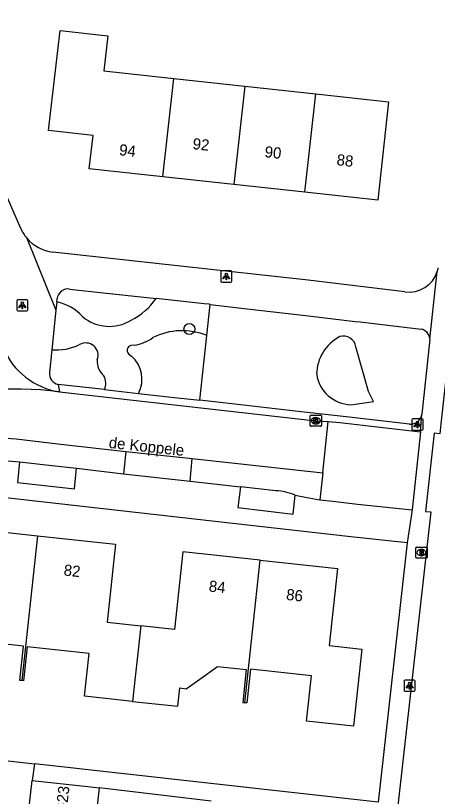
# Model space of a CAD drawing. Extents: x 162026 to 163499, y 387297 to 388169.
# Drawn here: x 162240.9 to 162278.6, y 387793.2 to 387863.1 of the extents above; entities that cross this region are included whole.
import ezdxf

# ---------------------------------------------------------------- set-up
doc = ezdxf.new("R2010")
doc.units = 0
for name, color, linetype in [('IMGEO_Boom', 7, 'Continuous'), ('IMGEO_Brandkraan', 7, 'Continuous'), ('IMGEO_Fietspad_gesloten', 7, 'Continuous'), ('IMGEO_Groenvoorziening', 7, 'Continuous'), ('IMGEO_Kolk', 7, 'Continuous'), ('IMGEO_Lichtpunt', 7, 'Continuous'), ('IMGEO_Openbare_ruimte_label', 7, 'Continuous'), ('IMGEO_Pand', 7, 'Continuous'), ('IMGEO_Pand_nummerreeks', 7, 'Continuous'), ('IMGEO_Parkeervlak_open', 7, 'Continuous'), ('IMGEO_Rijbaan_lokaal_open', 7, 'Continuous'), ('IMGEO_Voetpad_open', 7, 'Continuous')]:
    doc.layers.add(name, color=color, linetype=linetype)

msp = doc.modelspace()

# ---------------------------------------------------------------- linework, layer by layer
at = {"layer": 'IMGEO_Boom'}
msp.add_circle((162256.452, 387835.043), 0.489, dxfattribs=at)
at = {"layer": 'IMGEO_Brandkraan'}
for p, q in [((162276.715, 387814.598), (162276.715, 387815.45)), ((162276.79, 387815.524), (162277.642, 387815.524)), ((162277.203, 387815.304), (162277.228, 387815.304)), ((162277.716, 387815.45), (162277.716, 387814.598)), ((162277.642, 387814.524), (162276.79, 387814.524)), ((162277.226, 387814.744), (162277.201, 387814.744))]:
    msp.add_line(p, q, dxfattribs=at)
for points in [[(162276.715, 387814.598), (162276.715, 387815.45)], [(162276.79, 387815.524), (162277.642, 387815.524)], [(162277.063, 387815.224), (162277.063, 387814.824), (162277.276, 387814.824)], [(162277.294, 387815.224), (162277.063, 387815.224)], [(162277.242, 387815.143), (162277.188, 387815.143), (162277.188, 387815.067)], [(162277.188, 387815.067), (162277.241, 387815.067)], [(162277.25, 387814.991), (162277.188, 387814.991), (162277.188, 387814.91)], [(162277.188, 387814.91), (162277.25, 387814.91)], [(162277.716, 387815.45), (162277.716, 387814.598)], [(162277.642, 387814.524), (162276.79, 387814.524)]]:
    msp.add_lwpolyline(points, dxfattribs=at)
for centre, radius, start, end in [((162276.792, 387815.448), 0.0765, 91.55205, 178.44795), ((162276.792, 387815.448), 0.0765, 91.55205, 178.44795), ((162277.243, 387815.105), 0.0379, 267.82845, 90.93552), ((162277.251, 387814.95), 0.0404, 269.87594, 90.50774), ((162277.298, 387815.079), 0.145, 59.4692, 91.53667), ((162277.323, 387815.126), 0.0922, 285.51372, 58.15012), ((162277.328, 387814.934), 0.105, 301.31148, 78.98903), ((162277.64, 387815.448), 0.0765, 1.55205, 88.44795), ((162277.64, 387815.448), 0.0765, 1.55205, 88.44795), ((162276.792, 387814.6), 0.0765, 181.55205, 268.44795), ((162276.792, 387814.6), 0.0765, 181.55205, 268.44795), ((162277.282, 387815.075), 0.251, 268.66757, 293.53466), ((162277.64, 387814.6), 0.0765, 271.55205, 358.44795), ((162277.64, 387814.6), 0.0765, 271.55205, 358.44795)]:
    msp.add_arc(centre, radius, start, end, dxfattribs=at)
for centre, major_axis, ratio, start_param, end_param in [((162277.202, 387815.024), (-0.387, 0.002), 0.722429, 4.712389, 7.853982), ((162277.227, 387815.024), (-0.39, 0.002), 0.717154, 1.570796, 4.712389)]:
    msp.add_ellipse(centre, major_axis=major_axis, ratio=ratio, start_param=start_param, end_param=end_param, dxfattribs=at)
at = {"layer": 'IMGEO_Fietspad_gesloten'}
msp.add_lwpolyline([(162296.034, 387979.848), (162290.464, 387929.711), (162288.097, 387908.488), (162278.956, 387826.545), (162278.87, 387825.665), (162278.372, 387825.72), (162277.589, 387818.699), (162278.067, 387818.669), (162270.183, 387748.502), (162261.381, 387669.505), (162260.87, 387664.615)], dxfattribs=at)
at = {"layer": 'IMGEO_Groenvoorziening'}
for points in [[(162257.994, 387834.455), (162258.294, 387837.248)], [(162257.372, 387828.658), (162257.994, 387834.455)], [(162251.508, 387833.59), (162251.198, 387833.553)], [(162270.892, 387828.269), (162272.94, 387828.554), (162272.489, 387829.458), (162271.358, 387833.459)], [(162250.993, 387832.822), (162251.269, 387832.606)]]:
    msp.add_lwpolyline(points, dxfattribs=at)
for centre, radius, start, end in [((162243.587, 387833.056), 4.527, 43.12046, 77.31501), ((162248.633, 387841.065), 5.841, 296.30783, 325.7774), ((162249.278, 387838.98), 3.702, 229.84877, 301.67357), ((162255.79, 387829.102), 5.789, 67.62357, 116.82366), ((162247.173, 387832.697), 1.098, 338.10227, 120.25238), ((162250.942, 387837.38), 3.832, 278.49298, 305.70015), ((162271.67, 387830.955), 3.831, 117.34239, 179.37605), ((162270.237, 387833.268), 1.138, 9.66245, 106.63339), ((162244.497, 387838.155), 4.985, 265.75481, 295.20673), ((162251.303, 387833.129), 0.437, 103.96615, 224.70284), ((162249.478, 387830.551), 2.726, 332.17177, 48.93446), ((162249.938, 387832.173), 1.75, 176.27334, 229.34419), ((162270.985, 387831.444), 3.177, 188.09455, 268.32221), ((162247.631, 387830.2), 1.334, 334.40012, 28.972)]:
    msp.add_arc(centre, radius, start, end, dxfattribs=at)
at = {"layer": 'IMGEO_Kolk'}
for p, q in [((162267.268, 387826.407), (162267.268, 387827.259)), ((162267.343, 387827.333), (162268.195, 387827.333)), ((162267.756, 387827.113), (162267.781, 387827.113)), ((162268.269, 387827.259), (162268.269, 387826.407)), ((162268.195, 387826.333), (162267.343, 387826.333)), ((162267.779, 387826.553), (162267.754, 387826.553))]:
    msp.add_line(p, q, dxfattribs=at)
for points in [[(162267.268, 387826.407), (162267.268, 387827.259)], [(162267.343, 387827.333), (162268.195, 387827.333)], [(162267.589, 387827.033), (162267.712, 387827.033), (162267.712, 387826.882), (162267.842, 387827.033), (162268.006, 387827.033), (162267.86, 387826.882), (162268.013, 387826.633), (162267.861, 387826.633), (162267.776, 387826.797), (162267.712, 387826.73), (162267.712, 387826.633), (162267.589, 387826.633), (162267.589, 387827.033)], [(162268.269, 387827.259), (162268.269, 387826.407)], [(162268.195, 387826.333), (162267.343, 387826.333)]]:
    msp.add_lwpolyline(points, dxfattribs=at)
for centre, start, end in [((162267.345, 387827.257), 91.55205, 178.44795), ((162267.345, 387827.257), 91.55205, 178.44795), ((162268.193, 387827.257), 1.55205, 88.44795), ((162268.193, 387827.257), 1.55205, 88.44795), ((162267.345, 387826.409), 181.55205, 268.44795), ((162267.345, 387826.409), 181.55205, 268.44795), ((162268.193, 387826.409), 271.55205, 358.44795), ((162268.193, 387826.409), 271.55205, 358.44795)]:
    msp.add_arc(centre, 0.0765, start, end, dxfattribs=at)
for centre, major_axis, ratio, start_param, end_param in [((162267.755, 387826.833), (-0.387, 0.002), 0.722429, 4.712389, 7.853982), ((162267.78, 387826.833), (-0.39, 0.002), 0.717154, 1.570796, 4.712389)]:
    msp.add_ellipse(centre, major_axis=major_axis, ratio=ratio, start_param=start_param, end_param=end_param, dxfattribs=at)
at = {"layer": 'IMGEO_Lichtpunt'}
for p, q in [((162259.248, 387840.148), (162259.248, 387839.341)), ((162259.248, 387840.148), (162259.248, 387839.341)), ((162260.15, 387840.243), (162259.342, 387840.243)), ((162260.15, 387840.243), (162259.342, 387840.243)), ((162260.244, 387839.341), (162260.244, 387840.148)), ((162260.244, 387839.341), (162260.244, 387840.148)), ((162259.342, 387839.247), (162260.15, 387839.247)), ((162259.342, 387839.247), (162260.15, 387839.247)), ((162240.991, 387837.568), (162240.991, 387836.761)), ((162240.991, 387837.568), (162240.991, 387836.761)), ((162241.893, 387837.663), (162241.085, 387837.663)), ((162241.893, 387837.663), (162241.085, 387837.663)), ((162241.987, 387836.761), (162241.987, 387837.568)), ((162241.987, 387836.761), (162241.987, 387837.568)), ((162241.085, 387836.667), (162241.893, 387836.667)), ((162241.085, 387836.667), (162241.893, 387836.667)), ((162276.363, 387826.898), (162276.363, 387826.091)), ((162276.363, 387826.898), (162276.363, 387826.091)), ((162277.265, 387826.993), (162276.457, 387826.993)), ((162277.265, 387826.993), (162276.457, 387826.993)), ((162277.359, 387826.091), (162277.359, 387826.898)), ((162277.359, 387826.091), (162277.359, 387826.898)), ((162276.457, 387825.997), (162277.265, 387825.997)), ((162276.457, 387825.997), (162277.265, 387825.997)), ((162275.657, 387803.518), (162275.657, 387802.711)), ((162275.657, 387803.518), (162275.657, 387802.711)), ((162276.559, 387803.613), (162275.751, 387803.613)), ((162276.559, 387803.613), (162275.751, 387803.613)), ((162276.653, 387802.711), (162276.653, 387803.518)), ((162276.653, 387802.711), (162276.653, 387803.518)), ((162275.751, 387802.617), (162276.559, 387802.617)), ((162275.751, 387802.617), (162276.559, 387802.617))]:
    msp.add_line(p, q, dxfattribs=at)
for points in [[(162259.622, 387839.812), (162259.661, 387839.784), (162259.473, 387839.522), (162259.435, 387839.549), (162259.622, 387839.812)], [(162259.724, 387839.764), (162259.771, 387839.764), (162259.771, 387839.442), (162259.724, 387839.442), (162259.724, 387839.764)], [(162259.834, 387839.784), (162259.872, 387839.811), (162260.059, 387839.549), (162260.02, 387839.521), (162259.834, 387839.784)], [(162241.365, 387837.232), (162241.404, 387837.204), (162241.216, 387836.942), (162241.178, 387836.969), (162241.365, 387837.232)], [(162241.467, 387837.184), (162241.514, 387837.184), (162241.514, 387836.862), (162241.467, 387836.862), (162241.467, 387837.184)], [(162241.577, 387837.204), (162241.615, 387837.231), (162241.802, 387836.969), (162241.763, 387836.941), (162241.577, 387837.204)], [(162276.737, 387826.562), (162276.776, 387826.534), (162276.588, 387826.272), (162276.55, 387826.299), (162276.737, 387826.562)], [(162276.839, 387826.514), (162276.886, 387826.514), (162276.886, 387826.192), (162276.839, 387826.192), (162276.839, 387826.514)], [(162276.949, 387826.534), (162276.987, 387826.561), (162277.174, 387826.299), (162277.135, 387826.271), (162276.949, 387826.534)], [(162276.031, 387803.182), (162276.07, 387803.154), (162275.882, 387802.892), (162275.844, 387802.919), (162276.031, 387803.182)], [(162276.133, 387803.134), (162276.18, 387803.134), (162276.18, 387802.812), (162276.133, 387802.812), (162276.133, 387803.134)], [(162276.243, 387803.154), (162276.281, 387803.181), (162276.468, 387802.919), (162276.429, 387802.891), (162276.243, 387803.154)]]:
    msp.add_lwpolyline(points, dxfattribs=at)
for centre in [(162259.747, 387839.946), (162241.49, 387837.366), (162276.862, 387826.696), (162276.156, 387803.316)]:
    msp.add_circle(centre, 0.0994, dxfattribs=at)
for centre, start, end in [((162259.342, 387840.148), 90, 180), ((162259.342, 387840.148), 90, 180), ((162260.15, 387840.148), 0, 90), ((162260.15, 387840.148), 0, 90), ((162259.342, 387839.341), 180, 270), ((162259.342, 387839.341), 180, 270), ((162260.15, 387839.341), 270, 0), ((162260.15, 387839.341), 270, 360), ((162241.085, 387837.568), 90, 180), ((162241.085, 387837.568), 90, 180), ((162241.893, 387837.568), 0, 90), ((162241.893, 387837.568), 0, 90), ((162241.085, 387836.761), 180, 270), ((162241.085, 387836.761), 180, 270), ((162241.893, 387836.761), 270, 0), ((162241.893, 387836.761), 270, 360), ((162276.457, 387826.898), 90, 180), ((162276.457, 387826.898), 90, 180), ((162277.265, 387826.898), 0, 90), ((162277.265, 387826.898), 0, 90), ((162276.457, 387826.091), 180, 270), ((162276.457, 387826.091), 180, 270), ((162277.265, 387826.091), 270, 0), ((162277.265, 387826.091), 270, 360), ((162275.751, 387803.518), 90, 180), ((162275.751, 387803.518), 90, 180), ((162276.559, 387803.518), 0, 90), ((162276.559, 387803.518), 0, 90), ((162275.751, 387802.711), 180, 270), ((162275.751, 387802.711), 180, 270), ((162276.559, 387802.711), 270, 0), ((162276.559, 387802.711), 270, 360)]:
    msp.add_arc(centre, 0.0946, start, end, dxfattribs=at)
at = {"layer": 'IMGEO_Pand'}
for points in [[(162254.057, 387848.671), (162247.477, 387849.39), (162247.819, 387852.37), (162243.845, 387852.826), (162244.871, 387861.768), (162249.143, 387861.278), (162248.785, 387858.162), (162255.04, 387857.482)], [(162254.057, 387848.671), (162255.04, 387857.482)], [(162255.04, 387857.482), (162261.413, 387856.79)], [(162261.413, 387856.79), (162260.43, 387847.976)], [(162261.413, 387856.79), (162267.776, 387856.099)], [(162267.776, 387856.099), (162274.279, 387855.393), (162273.321, 387846.569), (162266.792, 387847.281)], [(162266.792, 387847.281), (162267.776, 387856.099)], [(162260.43, 387847.976), (162254.057, 387848.671)], [(162266.792, 387847.281), (162260.43, 387847.976)], [(162241.435, 387803.56), (162241.275, 387803.578), (162241.61, 387806.663), (162234.779, 387807.405), (162235.314, 387812.322), (162235.854, 387817.292), (162242.842, 387816.533)], [(162242.842, 387816.533), (162241.435, 387803.56)], [(162242.842, 387816.533), (162249.83, 387815.773), (162249.073, 387808.805), (162252.09, 387808.477)], [(162262.785, 387814.341), (162255.858, 387815.094), (162255.104, 387808.15), (162252.09, 387808.477)], [(162261.398, 387801.587), (162262.785, 387814.341)], [(162262.785, 387814.341), (162269.71, 387813.589), (162268.962, 387806.708), (162271.879, 387806.391), (162271.129, 387799.483), (162266.937, 387799.938), (162267.378, 387803.994), (162261.927, 387804.587), (162261.598, 387801.565), (162261.398, 387801.587)], [(162252.09, 387808.477), (162251.355, 387801.708)], [(162251.355, 387801.708), (162247.051, 387802.176), (162247.467, 387805.999), (162241.923, 387806.602), (162241.591, 387803.543), (162241.435, 387803.56)], [(162251.355, 387801.708), (162255.406, 387801.268), (162255.585, 387802.911), (162256.155, 387802.836), (162257.375, 387803.707), (162258.962, 387804.839), (162261.54, 387804.559), (162261.219, 387801.607), (162261.398, 387801.587)], [(162242.023, 387791.445), (162242.378, 387794.629)], [(162242.378, 387794.629), (162247.348, 387794.074), (162248.361, 387793.961)], [(162248.361, 387793.961), (162248.006, 387790.778)]]:
    msp.add_lwpolyline(points, dxfattribs=at)
at = {"layer": 'IMGEO_Parkeervlak_open'}
for points in [[(162241.24, 387823.141), (162244.161, 387822.82), (162246.34, 387822.571)], [(162264.182, 387820.559), (162261.027, 387820.917)]]:
    msp.add_lwpolyline(points, dxfattribs=at)
msp.add_arc((162263.995, 387815.733), 4.83, 66.40969, 87.78329, dxfattribs=at)
at = {"layer": 'IMGEO_Rijbaan_lokaal_open'}
for points in [[(162244.818, 387829.41), (162267.769, 387826.833), (162268.878, 387826.764)], [(162268.392, 387822.16), (162268.878, 387826.764)], [(162268.878, 387826.764), (162269.901, 387826.66), (162277.144, 387825.832)], [(162277.144, 387825.832), (162276.387, 387818.853)], [(162238.679, 387825.353), (162240.948, 387825.201), (162244.673, 387824.775), (162250.744, 387824.091)], [(162250.744, 387824.091), (162250.562, 387822.082)], [(162250.744, 387824.091), (162256.693, 387823.44)], [(162256.504, 387821.431), (162256.693, 387823.44)], [(162256.693, 387823.44), (162268.392, 387822.16)], [(162250.562, 387822.082), (162256.504, 387821.431)], [(162268.392, 387822.16), (162268.136, 387819.735)], [(162268.136, 387819.735), (162269.281, 387819.617), (162271.485, 387819.369), (162276.387, 387818.853)], [(162234.953, 387796.965), (162242.578, 387796.117)], [(162242.578, 387796.117), (162242.378, 387794.629)]]:
    msp.add_lwpolyline(points, dxfattribs=at)
for centre, radius, start, end in [((162245.852, 387835.92), 6.592, 202.9123, 260.97644), ((162240.931, 387800.369), 29.3, 82.37719, 108.9015)]:
    msp.add_arc(centre, radius, start, end, dxfattribs=at)
at = {"layer": 'IMGEO_Voetpad_open'}
for points in [[(162241.346, 387844.054), (162232.282, 387864.869)], [(162241.884, 387843.183), (162244.501, 387836.716)], [(162275.737, 387838.38), (162267.079, 387839.429), (162244.219, 387841.935)], [(162277.973, 387834.139), (162278.638, 387840.188)], [(162245.713, 387838.625), (162253.463, 387837.78)], [(162244.581, 387837.472), (162244.501, 387836.716)], [(162244.581, 387837.472), (162244.612, 387837.768)], [(162258.294, 387837.248), (162258.229, 387837.256), (162257.77, 387837.31), (162253.463, 387837.78)], [(162258.294, 387837.248), (162261.621, 387836.858), (162267.103, 387836.214), (162271.283, 387835.723), (162271.724, 387835.672), (162275.714, 387835.203), (162277.197, 387835.042)], [(162244.501, 387836.716), (162244.128, 387833.184)], [(162277.973, 387834.139), (162277.255, 387827.421)], [(162244.128, 387833.184), (162243.914, 387831.152)], [(162248.834, 387829.623), (162244.711, 387830.089)], [(162244.711, 387830.089), (162244.818, 387829.41)], [(162248.834, 387829.623), (162251.889, 387829.278)], [(162251.889, 387829.278), (162255.638, 387828.854), (162255.991, 387828.814), (162257.372, 387828.658)], [(162276.155, 387826.534), (162270.76, 387827.144), (162270.216, 387827.205), (162266.189, 387827.661), (162262.065, 387828.127), (162257.372, 387828.658)], [(162277.144, 387825.832), (162277.255, 387827.421)], [(162238.465, 387823.383), (162240.196, 387823.256), (162241.24, 387823.141)], [(162241.24, 387823.141), (162241.046, 387821.3), (162243.475, 387821.028), (162246.158, 387820.737), (162246.34, 387822.571)], [(162246.34, 387822.571), (162250.562, 387822.082)], [(162256.504, 387821.431), (162261.027, 387820.917)], [(162261.027, 387820.917), (162260.783, 387819.067), (162265.748, 387818.453), (162265.928, 387820.159)], [(162275.948, 387815.9), (162270.899, 387816.432), (162239.75, 387819.947)], [(162265.928, 387820.159), (162267.143, 387819.94), (162268.136, 387819.735)], [(162276.387, 387818.853), (162275.948, 387815.9)], [(162275.948, 387815.9), (162273.341, 387792.696)], [(162273.341, 387792.696), (162242.578, 387796.117)], [(162258.402, 387792.758), (162248.361, 387793.961)]]:
    msp.add_lwpolyline(points, dxfattribs=at)
for centre, radius, start, end in [((162244.574, 387845.446), 3.515, 203.32899, 220.07667), ((162244.604, 387845.463), 3.549, 219.97689, 263.77629), ((162276.128, 387840.984), 2.633, 261.45644, 342.40864), ((162276.047, 387841.003), 2.716, 342.53031, 349.87633), ((162245.586, 387837.652), 0.981, 82.59196, 173.20122), ((162276.964, 387834.057), 1.012, 4.65382, 76.69492), ((162244.934, 387831.087), 1.022, 176.32627, 257.39628), ((162276.241, 387827.554), 1.023, 265.20607, 352.55681)]:
    msp.add_arc(centre, radius, start, end, dxfattribs=at)

# ---------------------------------------------------------------- texts
at = {"layer": 'IMGEO_Openbare_ruimte_label'}
msp.add_text('de Koppele', height=1, rotation=353.856, dxfattribs=at).set_placement((162249.197, 387824.401))
at = {"layer": 'IMGEO_Pand_nummerreeks'}
for s, rotation, p in [('92', 353.64224, (162256.696, 387851.155)), ('94', 353.764, (162250.119, 387850.61)), ('90', 353.64224, (162263.144, 387850.436)), ('88', 353.64224, (162269.585, 387849.718)), ('82', 353.79708, (162245.158, 387812.982)), ('84', 353.8006, (162258.146, 387811.547)), ('86', 353.79922, (162265.072, 387810.794)), ('70/G23', 83.49273, (162245.224, 387789.717))]:
    msp.add_text(s, height=1, rotation=rotation, dxfattribs=at).set_placement(p)

doc.saveas('drawing.dxf')
